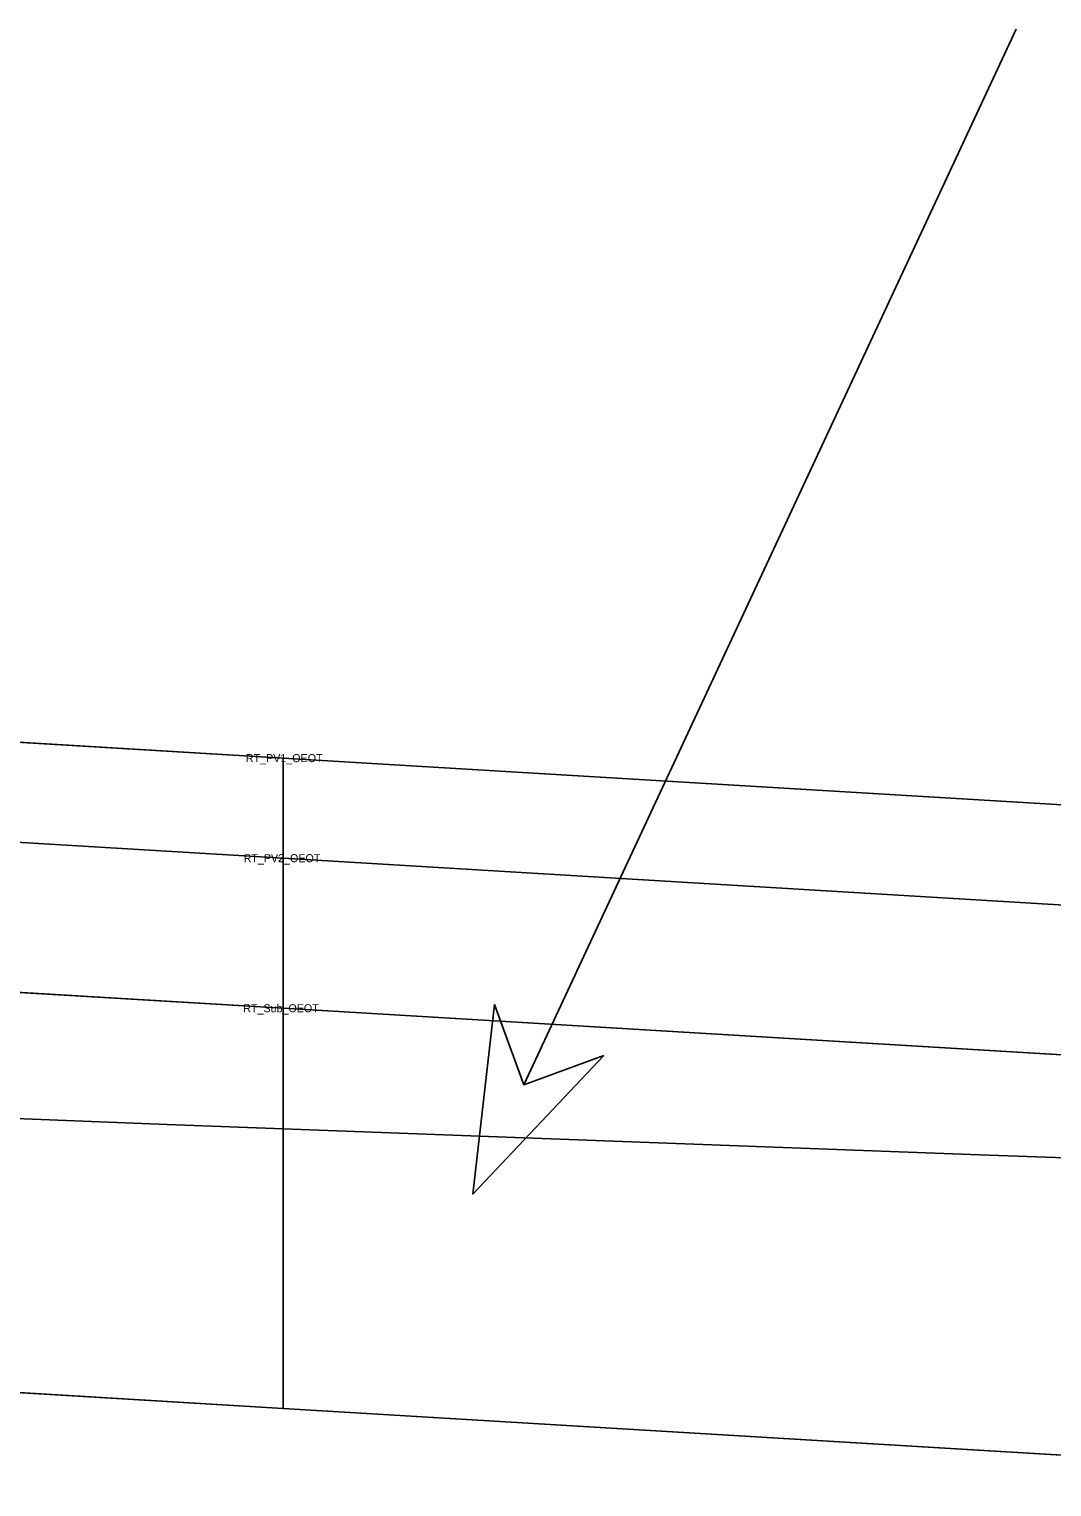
# Model space of a CAD drawing. Extents: x -516 to 303, y -10 to 5017.
# Drawn here: x 161.365 to 163.921, y 2006.605 to 2010.248 of the extents above; entities that cross this region are included whole.
import ezdxf

# ---------------------------------------------------------------- set-up
doc = ezdxf.new("R2010")
doc.units = 0
for name, color, linetype in [('Exist XS Ground Line', 7, 'Continuous'), ('Prop CMT Pvmt Course 1', 7, 'Continuous'), ('Prop CMT Pvmt Course 2', 7, 'Continuous'), ('Prop CMT Pvmt Course 3', 7, 'Continuous'), ('Prop CMT Pvmt Surface', 7, 'Continuous'), ('Prop CMT Pvmt Surface Shoulder', 7, 'Continuous'), ('Prop CMT Shld Paved Course 1', 7, 'Continuous'), ('Prop CMT Shld Paved Course 2', 7, 'Continuous'), ('Prop CMT Shld Paved Course 3', 7, 'Continuous'), ('Prop CMT Subgrade Earthwork', 7, 'Continuous'), ('Prop Road Sect_ Misc - Drafting Aid (solid line)', 7, 'Continuous'), ('Prop Road Sect_ Misc - Drafting Aid (Tx - small)', 7, 'Continuous'), ('Prop Road Sect_ Recs - UC Shallow (Outline)', 7, 'Continuous'), ('Prop Road Sect_ Recs - UC Shallow (Pattern)', 7, 'Continuous'), ('Scratch_Level_0', 7, 'Continuous')]:
    doc.layers.add(name, color=color, linetype=linetype)

msp = doc.modelspace()

# ---------------------------------------------------------------- linework, layer by layer
at = {"layer": 'Exist XS Ground Line'}
msp.add_lwpolyline([(158.4835, 2007.6479), (159.961, 2007.5813), (161.0579, 2007.5364), (161.7106, 2007.5109), (163.7403, 2007.435), (164.3584, 2007.4133), (164.8981, 2007.3863), (165.9538, 2007.3364), (168.7402, 2007.2595), (171.8286, 2007.0285), (177.0448, 2006.6472)], dxfattribs=at)
at = {"layer": 'Prop CMT Pvmt Course 1'}
for points in [[(150, 2009.1461), (162, 2008.4261)], [(162, 2008.1761), (150, 2008.896)], [(162, 2008.4261), (162, 2008.1761)]]:
    msp.add_lwpolyline(points, dxfattribs=at)
at = {"layer": 'Prop CMT Pvmt Course 2'}
for points in [[(162, 2008.1761), (150, 2008.896)], [(150, 2008.896), (162, 2008.1761)], [(162, 2008.1761), (162, 2008.1761)]]:
    msp.add_lwpolyline(points, dxfattribs=at)
at = {"layer": 'Prop CMT Pvmt Course 3'}
for points in [[(150, 2008.896), (162, 2008.1761)], [(162, 2007.8011), (150, 2008.521)], [(162, 2008.1761), (162, 2007.8011)]]:
    msp.add_lwpolyline(points, dxfattribs=at)
at = {"layer": 'Prop CMT Pvmt Surface'}
msp.add_line((150, 2009.1461), (162, 2008.4261), dxfattribs=at)
at = {"layer": 'Prop CMT Pvmt Surface Shoulder'}
msp.add_line((162, 2008.4261), (164.6, 2008.2701), dxfattribs=at)
at = {"layer": 'Prop CMT Shld Paved Course 1'}
for points in [[(162, 2008.4261), (164.6, 2008.2701), (164.866, 2008.0041)], [(162, 2008.1761), (162, 2008.4261)], [(164.866, 2008.0041), (162, 2008.1761)]]:
    msp.add_lwpolyline(points, dxfattribs=at)
at = {"layer": 'Prop CMT Shld Paved Course 2'}
for points in [[(162, 2008.1761), (164.866, 2008.0041)], [(164.866, 2008.0041), (162, 2008.1761)], [(162, 2008.1761), (162, 2008.1761)]]:
    msp.add_lwpolyline(points, dxfattribs=at)
at = {"layer": 'Prop CMT Shld Paved Course 3'}
for points in [[(162, 2008.1761), (164.866, 2008.0041)], [(162, 2007.8011), (162, 2008.1761)], [(165.2649, 2007.6052), (162, 2007.8011)]]:
    msp.add_lwpolyline(points, dxfattribs=at)
at = {"layer": 'Prop CMT Subgrade Earthwork'}
for p, q in [((150, 2008.521), (162, 2007.8011)), ((162, 2007.8011), (165.2649, 2007.6052))]:
    msp.add_line(p, q, dxfattribs=at)
at = {"layer": 'Prop Road Sect_ Misc - Drafting Aid (solid line)'}
for p, q in [((162, 2007.8011), (162, 2006.8011)), ((162, 2006.8011), (148, 2007.6411)), ((165.2649, 2006.6052), (162, 2006.8011))]:
    msp.add_line(p, q, dxfattribs=at)
at = {"layer": 'Prop Road Sect_ Misc - Drafting Aid (Tx - small)'}
msp.add_line((163.8315, 2010.2478), (162.6012, 2007.6099), dxfattribs=at)
msp.add_lwpolyline([(162.8014, 2007.6827), (162.4739, 2007.3368), (162.5284, 2007.8101), (162.6012, 2007.6099)], close=True, dxfattribs=at)
at = {"layer": 'Prop Road Sect_ Recs - UC Shallow (Outline)'}
msp.add_lwpolyline([(148, 2007.6411), (148, 2007.9593), (148.2019, 2007.9549), (149.3973, 2007.9221), (150, 2007.906), (150.7755, 2007.8854), (153.3472, 2007.8082), (154.1183, 2007.7912), (155.9076, 2007.7453), (157.6019, 2007.6791), (158.4835, 2007.6479), (159.961, 2007.5813), (161.0579, 2007.5364), (161.7106, 2007.5109), (163.7403, 2007.435), (164.3584, 2007.4133), (164.8981, 2007.3863), (165.9538, 2007.3364), (166.2649, 2007.3278), (166.2649, 2006.6052), (165.2649, 2006.6052), (162, 2006.8011)], close=True, dxfattribs=at)
at = {"layer": 'Prop Road Sect_ Recs - UC Shallow (Pattern)'}
msp.add_lwpolyline([(162, 2006.8011), (165.2649, 2006.6052), (166.2649, 2006.6052), (166.2649, 2007.3278), (165.9538, 2007.3364), (164.8981, 2007.3863), (164.3584, 2007.4133), (163.7403, 2007.435), (161.7106, 2007.5109), (161.0579, 2007.5364), (159.961, 2007.5813), (158.4835, 2007.6479), (157.6019, 2007.6791), (155.9076, 2007.7453), (154.1183, 2007.7912), (153.3472, 2007.8082), (150.7755, 2007.8854), (150, 2007.906), (149.3973, 2007.9221), (148.2019, 2007.9549), (148, 2007.9593), (148, 2007.6411), (162, 2006.8011)], dxfattribs=at)

# ---------------------------------------------------------------- texts
at = {"layer": 'Scratch_Level_0'}
for s, p in [('RT_PV1_OEOT', (161.9069, 2008.4161)), ('RT_PV3_OEOT', (161.9013, 2008.1661)), ('RT_PV2_OEOT', (161.9013, 2008.1661)), ('RT_Sub_OEOT', (161.9003, 2007.7911))]:
    msp.add_text(s, height=0.02, dxfattribs=at).set_placement(p)

doc.saveas('drawing.dxf')
